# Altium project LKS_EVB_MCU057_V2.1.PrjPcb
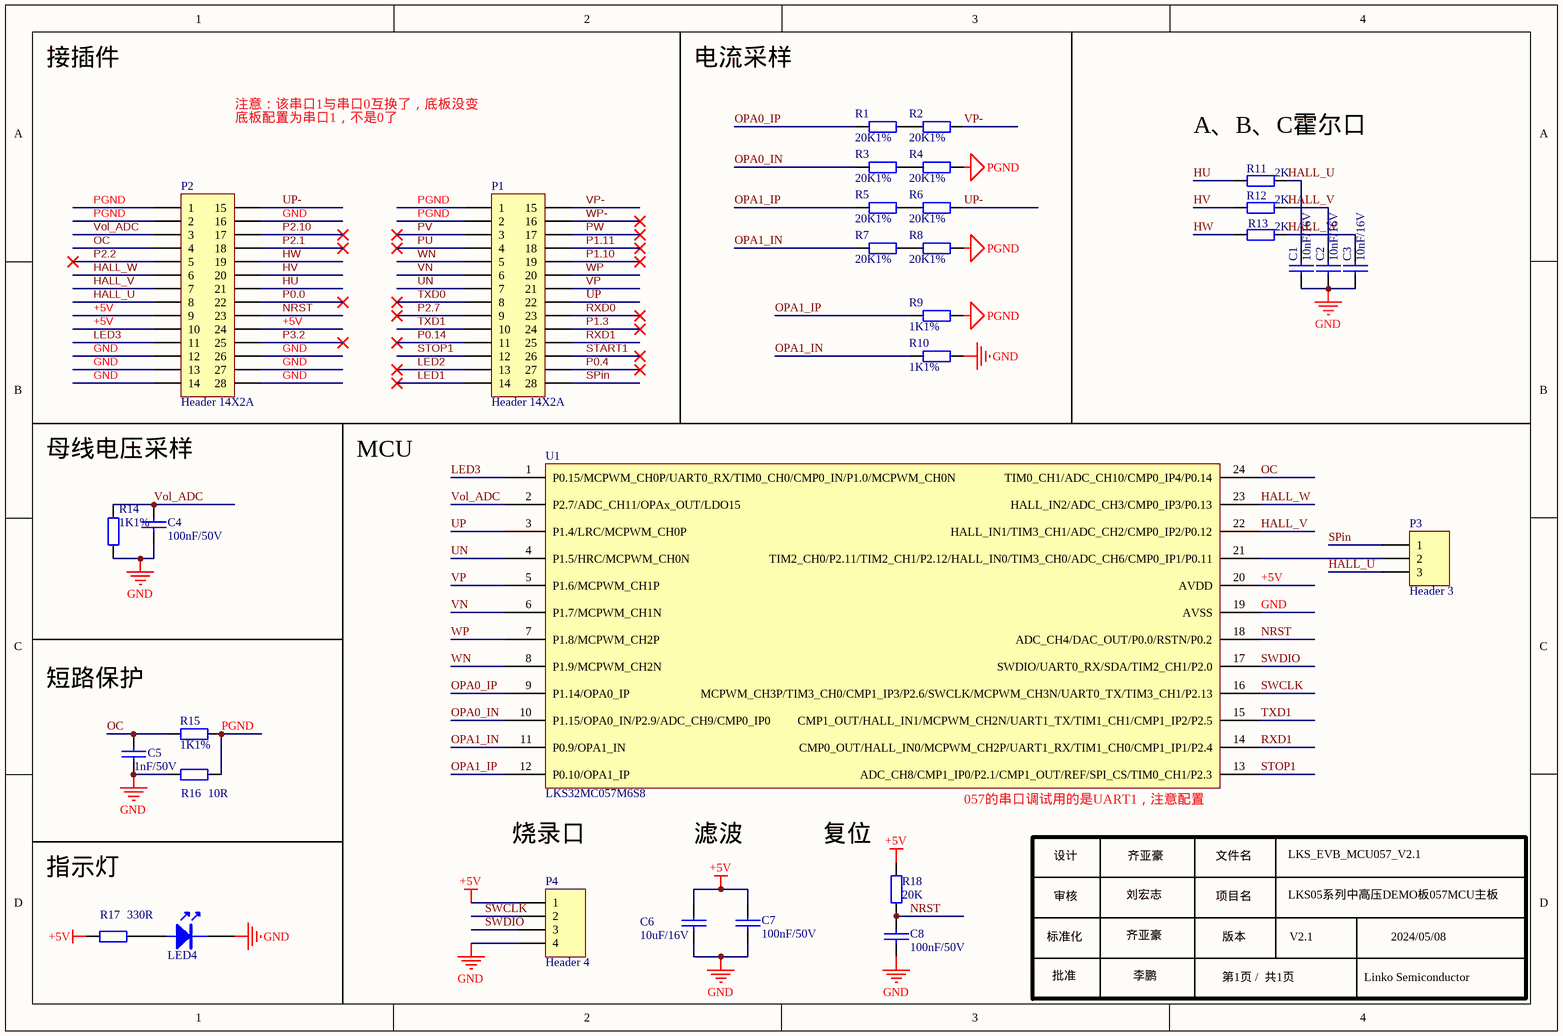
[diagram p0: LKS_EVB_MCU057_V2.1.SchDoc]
1 sheet, 32 parts. Net scope: global (net labels, ports and power ports of the same name join across sheets).
Board file: LKS_EVB_MCU057_V2.1.PcbDoc

## Sheet LKS_EVB_MCU057_V2.1.SchDoc
size A4; SheetNumber: 1; SheetTotal: 1

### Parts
C1  10nF/16V  [0603C]
C2  10nF/16V  [0603C]
C3  10nF/16V  [0603C]
C4  100nF/50V  [0603C]
C5  1nF/50V  [0603C]
C6  10uF/16V  [0603C]
C7  100nF/50V  [0603C]
C8  100nF/50V  [0603C]
LED4  LED  [LED 0603R]  (value not drawn)
P1  Header 14X2A  [HDR 2X14 底层]
P2  Header 14X2A  [HDR 2X14 底层]
P3  Header 3  [HDR 1X3]
P4  Header 4  [HDR 1X4]
R1  20K1%  [0603R]
R2  20K1%  [0603R]
R3  20K1%  [0603R]
R4  20K1%  [0603R]
R5  20K1%  [0603R]
R6  20K1%  [0603R]
R7  20K1%  [0603R]
R8  20K1%  [0603R]
R9  1K1%  [0603R]
R10  1K1%  [0603R]
R11  2K  [0603R]
R12  2K  [0603R]
R13  2K  [0603R]
R14  1K1%  [0603R]
R15  1K1%  [0603R]
R16  10R  [0603R]
R17  330R  [0603R]
R18  20K  [0603R]
U1  LKS32MC057M6S8  [SSOP24]

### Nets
+5V: C6.2 C7.2 P2.9 P2.10 P2.24 P4.1 R17.1 R18.2 U1.20(AVDD)
GND: C1.2 C2.2 C3.2 C4.1 C5.1 C6.1 C7.1 C8.2 LED4.2(K) P2.12 P2.13 P2.14 P2.16 P2.26 P2.27 P2.28 P4.4 R10.1 R14.1 R16.2 U1.19(AVSS)
PGND: P1.1 P1.2 P2.1 P2.2 R4.1 R8.1 R9.1 R15.2 R16.1
HALL_U: C1.1 P2.8 P3.3 R11.2
HALL_V: C2.1 P2.7 R12.2 U1.22(HALL_IN1/TIM3_CH1/ADC_CH2/CMP0_IP2/P0.12)
HALL_W: C3.1 P2.6 R13.2 U1.23(HALL_IN2/ADC_CH3/CMP0_IP3/P0.13)
HU: P2.21 R11.1
HV: P2.20 R12.1
HW: P2.19 R13.1
LED1: P1.14
LED2: P1.13
LED3: P2.11 U1.1(P0.15/MCPWM_CH0P/UART0_RX/TIM0_CH0/CMP0_IN/P1.0/MCPWM_CH0N)
NRST: C8.1 P2.23 R18.1 U1.18(ADC_CH4/DAC_OUT/P0.0/RSTN/P0.2)
OC: C5.2 P2.4 R15.1 U1.24(TIM0_CH1/ADC_CH10/CMP0_IP4/P0.14)
OPA0_IN: R3.2 U1.10(P1.15/OPA0_IN/P2.9/ADC_CH9/CMP0_IP0)
OPA0_IP: R1.2 U1.9(P1.14/OPA0_IP)
OPA1_IN: R7.2 R10.2 U1.11(P0.9/OPA1_IN)
OPA1_IP: R5.2 R9.2 U1.12(P0.10/OPA1_IP)
P0.0: P2.22
P0.4: P1.27
P0.14: P1.11
P1.3: P1.24
P1.10: P1.19
P1.11: P1.18
P2.1: P2.18
P2.2: P2.5
P2.7: P1.9
P2.10: P2.17
P3.2: P2.25
PU: P1.4
PV: P1.3
PW: P1.17
RXD0: P1.23
RXD1: P1.25 U1.14(CMP0_OUT/HALL_IN0/MCPWM_CH2P/UART1_RX/TIM1_CH0/CMP1_IP1/P2.4)
SPin: P1.28 P3.1
START1: P1.26
STOP1: P1.12 U1.13(ADC_CH8/CMP1_IP0/P2.1/CMP1_OUT/REF/SPI_CS/TIM0_CH1/P2.3)
SWCLK: P4.2 U1.16(MCPWM_CH3P/TIM3_CH0/CMP1_IP3/P2.6/SWCLK/MCPWM_CH3N/UART0_TX/TIM3_CH1/P2.13)
SWDIO: P4.3 U1.17(SWDIO/UART0_RX/SDA/TIM2_CH1/P2.0)
TXD0: P1.8
TXD1: P1.10 U1.15(CMP1_OUT/HALL_IN1/MCPWM_CH2N/UART1_TX/TIM1_CH1/CMP1_IP2/P2.5)
UN: P1.7 U1.4(P1.5/HRC/MCPWM_CH0N)
UP: P1.22 U1.3(P1.4/LRC/MCPWM_CH0P)
UP-: P2.15 R6.1
VN: P1.6 U1.6(P1.7/MCPWM_CH1N)
Vol_ADC: C4.2 P2.3 R14.2 U1.2(P2.7/ADC_CH11/OPAx_OUT/LDO15)
VP: P1.21 U1.5(P1.6/MCPWM_CH1P)
VP-: P1.15 R2.1
WN: P1.5 U1.8(P1.9/MCPWM_CH2N)
WP: P1.20 U1.7(P1.8/MCPWM_CH2P)
WP-: P1.16
NetLED4_1: LED4.1(A) R17.2
NetP3_2: P3.2 U1.21(TIM2_CH0/P2.11/TIM2_CH1/P2.12/HALL_IN0/TIM3_CH0/ADC_CH6/CMP0_IP1/P0.11)
NetR1_1: R1.1 R2.2
NetR3_1: R3.1 R4.2
NetR5_1: R5.1 R6.2
NetR7_1: R7.1 R8.2

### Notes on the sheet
- 接插件
- 注意：该串口1与串口0互换了，底板没变
- 电流采样
- 底板配置为串口1，不是0了
- (near R11) A、B、C霍尔口
- 母线电压采样
- MCU
- 短路保护
- 烧录口
- 滤波
- 复位
- (near U1) 057的串口调试用的是UART1，注意配置
- 指示灯
- 设计
- 审核
- 刘宏志
- 齐亚豪
- 文件名
- 项目名
- LKS_EVB_MCU057_V2.1
- LKS05系列中高压DEMO板057MCU主板
- 标准化
- 批准
- 李鹏
- 版本
- 第1页 /  共1页
- V2.1
- Linko Semiconductor
- 2024/05/08

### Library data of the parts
C1-C3 = CAP: Capacitor
C4-C8 = C: Capacitor
LED4 = LED: LED_Light
P1 P2 = Header 14X2A: Header, 14-Pin, Dual row
P3 = Header 3: Header, 3-Pin
P4 = Header 4: Header, 4-Pin
R1-R16 R18 = Res: Resistor; Value: K
R17 = Res: Resistor; Value: 330
U1 = LKS32MC057M6S8: 芯片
